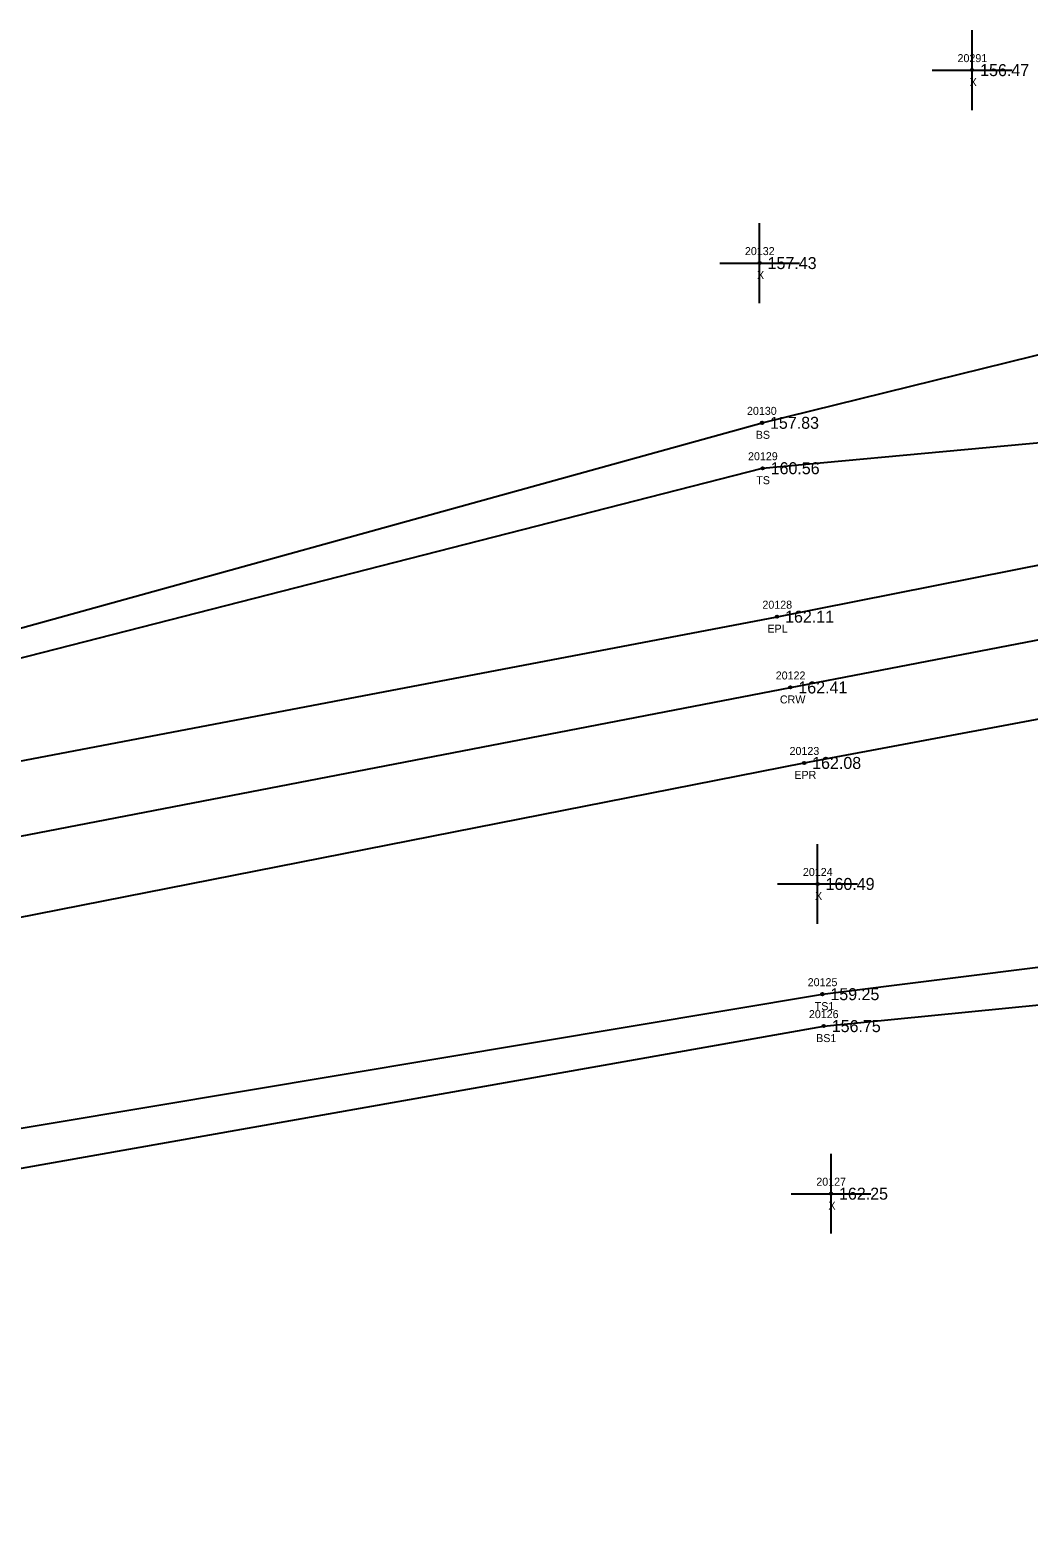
# Model space of a CAD drawing. Extents: x 2381545 to 2382928, y 1029933 to 1030589.
# Drawn here: x 2382022.9 to 2382147.9, y 1030248.4 to 1030437.2 of the extents above; entities that cross this region are included whole.
import ezdxf

# ---------------------------------------------------------------- set-up
doc = ezdxf.new("R2010")
doc.units = 0
for name, color, linetype in [('RD_DTM_BkLn1', 7, 'Continuous'), ('RD_DTM_BkLn2', 7, 'Continuous'), ('RD_DTM_BkLn_txCode', 7, 'Continuous'), ('RD_EX_Misc', 7, 'Continuous'), ('RD_EX_Misc_txCode', 7, 'Continuous'), ('RD_EX_Road', 7, 'Continuous'), ('RD_EX_Road_txCode', 7, 'Continuous'), ('RD_EX_TX_Misc_ELEV', 7, 'Continuous'), ('RD_EX_TX_Road_ELEV', 7, 'Continuous'), ('RD_HC_Survey_ELEV', 7, 'Continuous'), ('RD_HC_Survey_txCode', 7, 'Continuous'), ('RD_SMD_Locator', 7, 'Continuous')]:
    doc.layers.add(name, color=color, linetype=linetype)

msp = doc.modelspace()

# ---------------------------------------------------------------- linework, layer by layer
at = {"layer": 'RD_DTM_BkLn1'}
msp.add_lwpolyline([(2381547.18, 1030259.1), (2381595.71, 1030262.71), (2381646.12, 1030268.56), (2381695.78, 1030276.09), (2381799.52, 1030294.49), (2381897.44, 1030312.39), (2382008.24, 1030333.66), (2382118.08, 1030354.86), (2382202.13, 1030371.04)], dxfattribs=at)
at = {"layer": 'RD_DTM_BkLn2'}
for points in [[(2381793.09, 1030313.94), (2381875.92, 1030331.56), (2381878.21, 1030338.59), (2381904.22, 1030343.93), (2381908.67, 1030338.54), (2382000.53, 1030356.42), (2382114.53, 1030387.99), (2382160.73, 1030399.39)], [(2381904.22, 1030343.93), (2381906.64, 1030333.65), (2382003.16, 1030353.83), (2382114.61, 1030382.31), (2382198.59, 1030390.09), (2382200, 1030380.28)], [(2381785.89, 1030275.89), (2381871.01, 1030288.93), (2381880.52, 1030282.55), (2381901.68, 1030286.01), (2382013.28, 1030298.25), (2382122.09, 1030316.46), (2382195.01, 1030325.62), (2382206, 1030331.71), (2382212.25, 1030344.58), (2382207.28, 1030357.44), (2382204.69, 1030361.31)], [(2381786.8, 1030272.08), (2381870.97, 1030285.18), (2381880.6, 1030281.02), (2381901.08, 1030282.53), (2382011.65, 1030292.89), (2382122.26, 1030312.46), (2382194.74, 1030319.65), (2382207.56, 1030328.92), (2382216.83, 1030343.34)]]:
    msp.add_lwpolyline(points, dxfattribs=at)
at = {"layer": 'RD_EX_Misc'}
for p, q in [((2382140.84, 1030427.15), (2382140.84, 1030437.15)), ((2382135.84, 1030432.15), (2382145.84, 1030432.15)), ((2382114.23, 1030402.99), (2382114.23, 1030412.99)), ((2382109.23, 1030407.99), (2382119.23, 1030407.99)), ((2382121.49, 1030325.26), (2382121.49, 1030335.26)), ((2382116.49, 1030330.26), (2382126.49, 1030330.26)), ((2382123.17, 1030286.48), (2382123.17, 1030296.48)), ((2382118.17, 1030291.48), (2382128.17, 1030291.48))]:
    msp.add_line(p, q, dxfattribs=at)
at = {"layer": 'RD_EX_Road'}
for points in [[(2381547.21, 1030268.01), (2381595.28, 1030271.86), (2381645.28, 1030277.12), (2381675.41, 1030281.84), (2381694.68, 1030285.03), (2381797.68, 1030303.35), (2381895.95, 1030322.08), (2382005.53, 1030342.57), (2382116.42, 1030363.72), (2382200, 1030380.28), (2382202.13, 1030371.04)], [(2381547.49, 1030248.39), (2381596.55, 1030252.33), (2381646.64, 1030258.33), (2381698.19, 1030266.34), (2381800.73, 1030284.35), (2381899.22, 1030302.47), (2382010.02, 1030323.79), (2382119.81, 1030345.41), (2382204.69, 1030361.31), (2382202.13, 1030371.04)]]:
    msp.add_lwpolyline(points, dxfattribs=at)
at = {"layer": 'RD_SMD_Locator'}
for centre in [(2382140.84, 1030432.15), (2382114.23, 1030407.99), (2382114.53, 1030387.99), (2382114.61, 1030382.31), (2382116.42, 1030363.72), (2382118.08, 1030354.86), (2382119.81, 1030345.41), (2382121.49, 1030330.26), (2382122.09, 1030316.46), (2382122.26, 1030312.46), (2382123.17, 1030291.48)]:
    msp.add_circle(centre, 0.15, dxfattribs=at)

# ---------------------------------------------------------------- texts
at = {"layer": 'RD_DTM_BkLn_txCode'}
for s, p in [('20130', (2382112.65, 1030388.99)), ('BS', (2382113.75, 1030385.99)), ('20129', (2382112.78, 1030383.31)), ('TS', (2382113.82, 1030380.31)), ('20125', (2382120.25, 1030317.46)), ('TS1', (2382121.13, 1030314.46)), ('20126', (2382120.4, 1030313.46)), ('BS1', (2382121.31, 1030310.46))]:
    msp.add_text(s, height=1, dxfattribs=at).set_placement(p)
at = {"layer": 'RD_EX_Misc_txCode'}
for s, p in [('20291', (2382139.01, 1030433.15)), ('X', (2382140.53, 1030430.15)), ('20132', (2382112.39, 1030408.99)), ('X', (2382113.91, 1030405.99)), ('20124', (2382119.65, 1030331.26)), ('X', (2382121.17, 1030328.26)), ('20127', (2382121.33, 1030292.48)), ('X', (2382122.85, 1030289.48))]:
    msp.add_text(s, height=1, dxfattribs=at).set_placement(p)
at = {"layer": 'RD_EX_Road_txCode'}
for s, p in [('20128', (2382114.58, 1030364.72)), ('EPL', (2382115.21, 1030361.72)), ('20123', (2382117.98, 1030346.41)), ('EPR', (2382118.58, 1030343.41))]:
    msp.add_text(s, height=1, dxfattribs=at).set_placement(p)
at = {"layer": 'RD_EX_TX_Misc_ELEV'}
for s, p in [('156.47', (2382141.84, 1030431.4)), ('157.43', (2382115.23, 1030407.24)), ('157.83', (2382115.53, 1030387.24)), ('160.56', (2382115.61, 1030381.56)), ('160.49', (2382122.49, 1030329.51)), ('159.25', (2382123.09, 1030315.71)), ('156.75', (2382123.26, 1030311.71)), ('162.25', (2382124.17, 1030290.73))]:
    msp.add_text(s, height=1.5, dxfattribs=at).set_placement(p)
at = {"layer": 'RD_EX_TX_Road_ELEV'}
for s, p in [('162.11', (2382117.42, 1030362.97)), ('162.08', (2382120.81, 1030344.66))]:
    msp.add_text(s, height=1.5, dxfattribs=at).set_placement(p)
at = {"layer": 'RD_HC_Survey_ELEV'}
msp.add_text('162.41', height=1.5, dxfattribs=at).set_placement((2382119.08, 1030354.11))
at = {"layer": 'RD_HC_Survey_txCode'}
for s, p in [('20122', (2382116.25, 1030355.86)), ('CRW', (2382116.77, 1030352.86))]:
    msp.add_text(s, height=1, dxfattribs=at).set_placement(p)

doc.saveas('drawing.dxf')
